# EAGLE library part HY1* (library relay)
Non-polarized 1 Form C Relay NAiS Source: http://www.mew-europe.com/.. en_ds_61012_0000.pdf
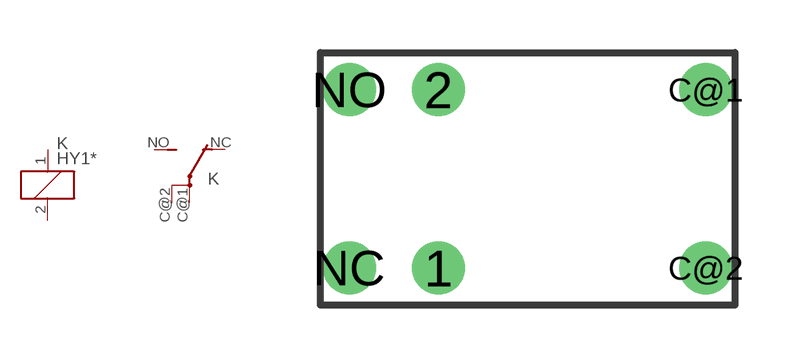
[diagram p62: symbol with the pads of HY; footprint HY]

Designator prefix K; gates 1=K 2=U1

## HY1-1.5V (OC_FARNELL: unknown; OC_NEWARK: unknown), HY1-3V (MF: AROMAT/ MATSUSHITA; MPN: HY1-3V; OC_FARNELL: unknown; OC_NEWARK: 10C6690), HY1-4.5V (OC_FARNELL: unknown; OC_NEWARK: unknown), HY1-5V (MF: AROMAT/ MATSUSHITA; MPN: HY1-5V; OC_FARNELL: unknown; OC_NEWARK: 10C6692), HY1-6V (MF: AROMAT/ MATSUSHITA; MPN: HY1-6V; OC_FARNELL: unknown; OC_NEWARK: 10C6693), HY1-9V (MF: AROMAT/ MATSUSHITA; MPN: HY1-9V; OC_FARNELL: unknown; OC_NEWARK: 10C6694), HY1-12V (MF: AROMAT/ MATSUSHITA; MPN: HY1-12V; OC_FARNELL: unknown; OC_NEWARK: 10C6688), HY1-24V (MF: AROMAT/ MATSUSHITA; MPN: HY1-24V; OC_FARNELL: unknown; OC_NEWARK: 10C6689), HY1Z-1.5V (OC_FARNELL: unknown; OC_NEWARK: unknown), HY1Z-3V (OC_FARNELL: unknown; OC_NEWARK: unknown), HY1Z-4.5V (MF: AROMAT/ MATSUSHITA; MPN: HY1Z-4.5V; OC_FARNELL: unknown; OC_NEWARK: 10C6707), HY1Z-5V (MF: AROMAT/ MATSUSHITA; MPN: HY1Z-5V; OC_FARNELL: unknown; OC_NEWARK: 52F9234), HY1Z-6V (OC_FARNELL: unknown; OC_NEWARK: unknown), HY1Z-9V (MF: AROMAT/ MATSUSHITA; MPN: HY1Z-9V; OC_FARNELL: unknown; OC_NEWARK: 10C6709), HY1Z-12V (MF: AROMAT/ MATSUSHITA; MPN: HY1Z-12V; OC_FARNELL: unknown; OC_NEWARK: 10C6704), HY1Z-24V (MF: AROMAT/ MATSUSHITA; MPN: HY1Z-24V; OC_FARNELL: unknown; OC_NEWARK: 10C6705)  [HY]
1  1:1  pas
2  1:2  pas
C@1  2:P  pas
C@2  2:P  pas
NC  2:O  pas
NO  2:S  pas

## Footprint HY (pad centres in mm)
Non-polarized 1 Form C Relay NAiS Source: http://www.mew-europe.com/.. en_ds_61012_0000.pdf
drill 1 round: 1 -2.54,-2.54; 2 -2.54,2.54; C@1 5.08,2.54; C@2 5.08,-2.54; NC -5.08,-2.54; NO -5.08,2.54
